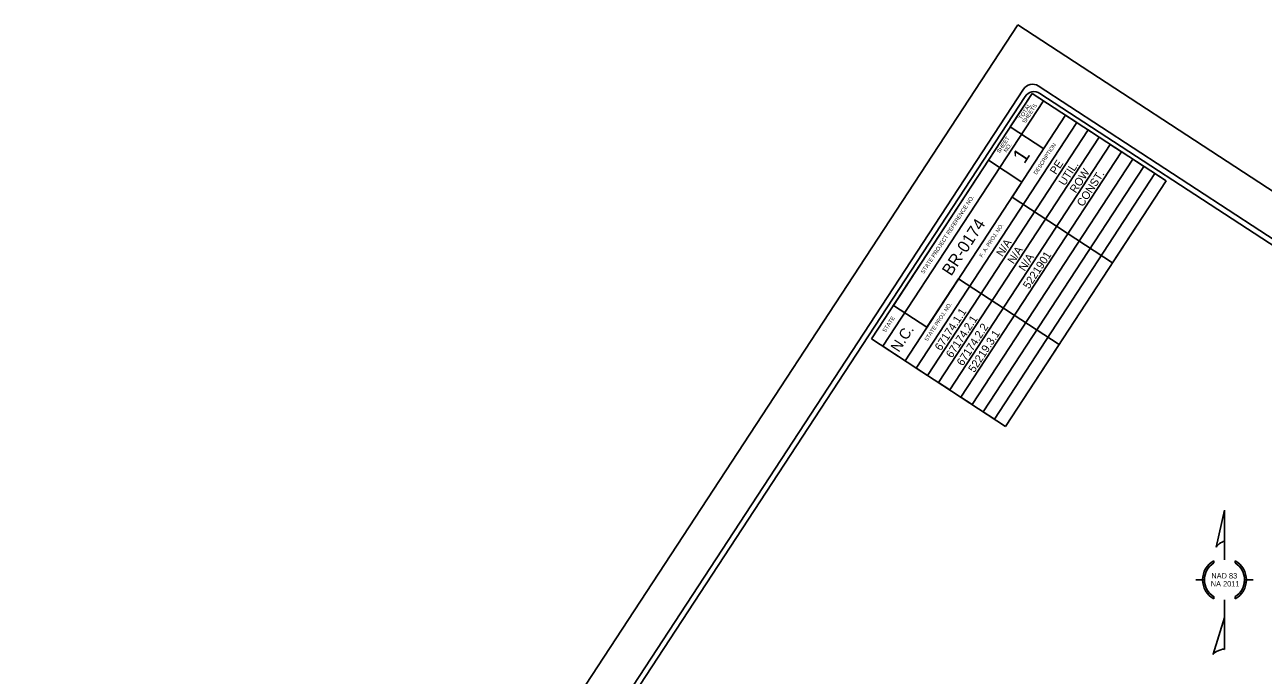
# Model space of a CAD drawing. Extents: x 1190029 to 2382315, y 163128 to 334830.
# Drawn here: x 2378613 to 2380933, y 333329 to 334549 of the extents above; entities that cross this region are included whole.
import ezdxf

# ---------------------------------------------------------------- set-up
doc = ezdxf.new("R2010")
doc.units = 0
for name, color, linetype in [('Exist Utilities Telephone UG FO SUE LOS B Text', 7, 'Continuous'), ('P_NCDOT_Vertical_Profile_Strip_Grade', 7, 'Continuous'), ('Sheet_Plan_CELL', 7, 'Continuous'), ('z - Construction', 7, 'Continuous')]:
    doc.layers.add(name, color=color, linetype=linetype)

msp = doc.modelspace()

# ---------------------------------------------------------------- linework, layer by layer
at = {"layer": 'Exist Utilities Telephone UG FO SUE LOS B Text'}
for p, q in [((2380483.9, 334428.7), (2378727.4, 331741.9)), ((2382194, 333334.6), (2380511.6, 334434.5)), ((2380486.9, 334414.8), (2378796.1, 331828.5)), ((2380500.1, 334420.5), (2380199.2, 333960.1)), ((2380220.1, 333946.5), (2380521.1, 334406.8)), ((2380500.1, 334420.5), (2380459.1, 334357.7)), ((2380521.1, 334406.8), (2380500.1, 334420.5)), ((2380751.2, 334256.3), (2380500.1, 334420.5)), ((2381870.5, 333534.1), (2380514.6, 334420.6)), ((2380562.9, 334379.5), (2380261.9, 333919.1)), ((2380583.8, 334365.8), (2380562.9, 334379.5)), ((2380282.9, 333905.4), (2380583.8, 334365.8)), ((2380459.1, 334357.7), (2380521.9, 334316.7)), ((2380604.8, 334352.1), (2380303.8, 333891.7)), ((2380324.7, 333878.1), (2380625.7, 334338.4)), ((2380625.7, 334338.4), (2380604.8, 334352.1)), ((2380646.6, 334324.7), (2380345.6, 333864.4)), ((2380366.6, 333850.7), (2380667.5, 334311.1)), ((2380667.5, 334311.1), (2380646.6, 334324.7)), ((2380240.2, 334022.9), (2380418.1, 334295)), ((2380688.5, 334297.4), (2380387.5, 333837)), ((2380408.4, 333823.3), (2380709.4, 334283.7)), ((2380418.1, 334295), (2380480.8, 334253.9)), ((2380709.4, 334283.7), (2380688.5, 334297.4)), ((2380730.3, 334270), (2380429.3, 333809.7)), ((2380751.2, 334256.3), (2380730.3, 334270)), ((2380450.3, 333796), (2380751.2, 334256.3)), ((2380480.8, 334253.9), (2380462.5, 334226)), ((2380650.9, 334102.8), (2380751.2, 334256.3)), ((2380462.5, 334226), (2380650.9, 334102.8)), ((2380362.3, 334072.5), (2380303, 333981.9)), ((2380550.6, 333949.4), (2380362.3, 334072.5)), ((2380303, 333981.9), (2380240.2, 334022.9)), ((2380199.2, 333960.1), (2380450.3, 333796)), ((2380261.9, 333919.1), (2380220.1, 333946.5)), ((2380450.3, 333796), (2380550.6, 333949.4)), ((2380303.8, 333891.7), (2380282.9, 333905.4)), ((2380345.6, 333864.4), (2380324.7, 333878.1)), ((2380387.5, 333837), (2380366.6, 333850.7)), ((2380429.3, 333809.7), (2380408.4, 333823.3))]:
    msp.add_line(p, q, dxfattribs=at)
for centre in [(2380500.7, 334417.8), (2380503.7, 334403.8)]:
    msp.add_arc(centre, 20, 56.8248, 146.8248, dxfattribs=at)
at = {"layer": 'P_NCDOT_Vertical_Profile_Strip_Grade'}
for p, q in [((2380844.7, 333569.4), (2380860.5, 333638.9)), ((2380860.5, 333638.9), (2380860.5, 333638.9)), ((2380860.5, 333638.9), (2380860.5, 333638.9)), ((2380860.5, 333638.9), (2380860.5, 333577.9)), ((2380860.5, 333545.7), (2380860.5, 333638.9)), ((2380860.5, 333577.9), (2380860.5, 333579.7)), ((2380860.5, 333579.7), (2380860.6, 333579.7)), ((2380840.4, 333543.9), (2380840.4, 333539.8)), ((2380840.4, 333543.9), (2380840.4, 333543.9)), ((2380880.7, 333539.8), (2380880.7, 333543.9)), ((2380806.5, 333508.2), (2380823, 333508.2)), ((2380823, 333508.2), (2380819.5, 333508.2)), ((2380819.5, 333508.2), (2380823, 333508.2)), ((2380898, 333508.2), (2380914.5, 333508.2)), ((2380898, 333508.2), (2380901.5, 333508.2)), ((2380901.5, 333508.2), (2380898, 333508.2)), ((2380840.4, 333476.6), (2380840.4, 333472.5)), ((2380880.7, 333472.5), (2380880.7, 333476.6)), ((2380880.7, 333472.5), (2380880.7, 333472.5)), ((2380860.5, 333377.5), (2380860.5, 333470.7)), ((2380860.5, 333437.5), (2380839, 333368.6)), ((2380860.5, 333377.5), (2380860.5, 333437.5))]:
    msp.add_line(p, q, dxfattribs=at)
for radius, start, end in [(41, 119.4342, 240.5658), (41, 299.5204, 60.4796), (41, 0, 60.4796), (37.5, 122.5032, 237.4968), (37.5, 302.6006, 57.3994), (37.5, 0, 57.3994), (41, 180, 240.5658), (37.5, 180, 237.4968)]:
    msp.add_arc((2380860.5, 333508.2), radius, start, end, dxfattribs=at)
for centre, major_axis, ratio, start_param, end_param in [((2380852.5, 333573.7), (7.98, 6.12), 0.261723, 6.225794, 8.917625), ((2380860.5, 333508.2), (0, 41.1), 0.998737, 0.514018, 1.570796), ((2380860.5, 333508.2), (0, 37.5), 0.998737, 0.567287, 1.570796), ((2380860.5, 333508.2), (0, 37.5), 0.998737, 3.71058, 4.712389), ((2380860.5, 333508.2), (0, 41.1), 0.998737, 3.657116, 4.712389), ((2380849.7, 333372.6), (10.8, 4.9), 0.225493, 6.280036, 9.220301)]:
    msp.add_ellipse(centre, major_axis=major_axis, ratio=ratio, start_param=start_param, end_param=end_param, dxfattribs=at)
at = {"layer": 'z - Construction'}
for p, q in [((2380473.1, 334549.3), (2378612.6, 331703.5)), ((2382314.5, 333345.4), (2380473.1, 334549.3))]:
    msp.add_line(p, q, dxfattribs=at)

# ---------------------------------------------------------------- texts
at = {"layer": 'Exist Utilities Telephone UG FO SUE LOS B Text'}
for s, height, p in [('SHEETS', 7.5, (2380487.1, 334363.3)), ('TOTAL', 7.5, (2380480.5, 334370.7)), ('SHEET', 7.5, (2380439.5, 334307.5)), ('NO.', 7.5, (2380452.3, 334309)), ('1', 29, (2380485.6, 334287)), ('DESCRIPTION', 7.2, (2380508.2, 334267.5)), ('STATE PROJECT REFERENCE NO.', 7.5, (2380297.1, 334081.5)), ('F. A. PROJ. NO.', 7.2, (2380406.6, 334112.2)), ('STATE PROJ. NO.', 7.2, (2380303.7, 333954.8)), ('STATE', 7.5, (2380225.1, 333971.4)), ('N.C.', 20, (2380250.3, 333933.7))]:
    msp.add_text(s, height=height, rotation=56.8248, dxfattribs=at).set_placement(p)
at = {"layer": 'P_NCDOT_Vertical_Profile_Strip_Grade'}
for s, p in [('NAD 83', (2380835.9, 333510.7)), ('NA 2011', (2380834.8, 333495.7))]:
    msp.add_text(s, height=10, dxfattribs=at).set_placement(p)
at = {"layer": 'Sheet_Plan_CELL'}
for s, height, p in [('    PE    ', 15, (2380532.5, 334248.4)), ('   UTIL.  ', 15, (2380552, 334232.2)), ('    ROW   ', 15, (2380569.7, 334213.6)), ('   CONST.  ', 15, (2380585.9, 334192.8)), ('  BR-0174 ', 22.5, (2380339.3, 334062.6)), ('     N/A     ', 15, (2380429, 334089.8)), ('     N/A     ', 15, (2380450, 334076.1)), ('   5221901   ', 15, (2380485.1, 334038.5)), ('     N/A     ', 15, (2380470.9, 334062.5)), ('67174.1.1', 15, (2380329, 333936.7)), ('67174.2.1', 15, (2380349.9, 333923.1)), ('67174.2.2', 15, (2380370.1, 333908.2)), ('52219.3.1', 15, (2380391.7, 333895.7))]:
    msp.add_text(s, height=height, rotation=56.8248, dxfattribs=at).set_placement(p)

doc.saveas('drawing.dxf')
